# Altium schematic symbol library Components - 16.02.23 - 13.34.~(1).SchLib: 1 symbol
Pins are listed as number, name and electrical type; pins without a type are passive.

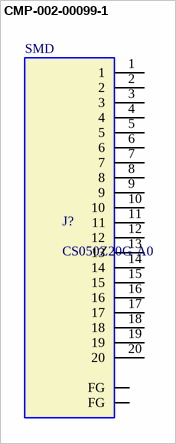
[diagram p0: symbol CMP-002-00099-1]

## CMP-002-00099-1
designator J?, comment CS050Z20G-A0  PACKAGE: SMD
20 Position FPC Connector Contacts, Top/Bottom, 0.50mm, Surface Mount, Right Angle; MFG: Dian Wei; MFGPN: 8.01A0.020200; SUBSTITUTE: EXACT; LOAD: ALL
footprint 20POS_0.5MM_R
footprint 20POS_0.5MM_L (8pin .05mm pitch connector)
pins: 1 "something", 2, 3, 4, 5, 6, 7, 8, 9, 10, 11, 12, 13, 14, 15, 16, 17, 18, 19, 20, FG1 FG, FG2 FG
